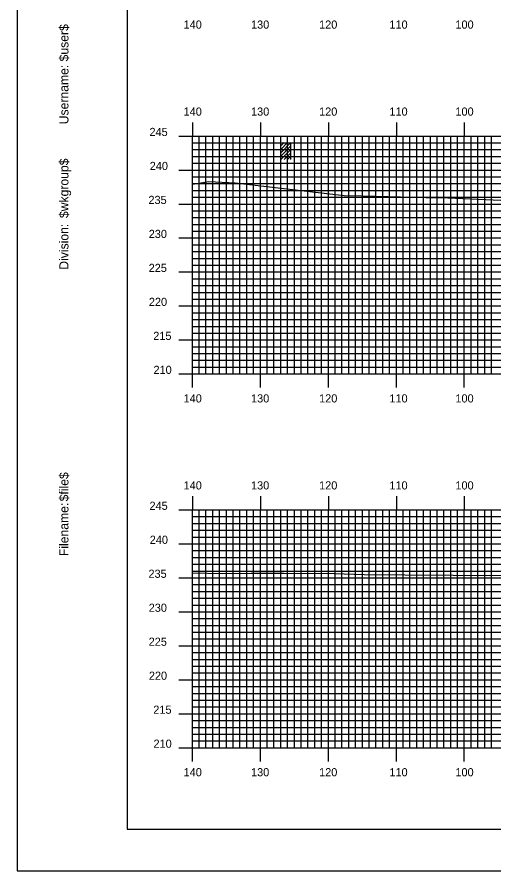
# Model space of a CAD drawing. Extents: x 1802323 to 1802666, y 442591 to 442811.
# Drawn here: x 1802322.8 to 1802393, y 442590.5 to 442716.2 of the extents above; entities that cross this region are included whole.
import ezdxf

# ---------------------------------------------------------------- set-up
doc = ezdxf.new("R2010")
doc.units = 0
for name, color, linetype in [('BORDER', 7, 'Continuous'), ('H_V ANNOTATION', 7, 'Continuous'), ('M_Buildings_Attachments', 7, 'Continuous'), ('MAJOR', 7, 'Continuous'), ('MINOR', 7, 'Continuous'), ('PLOT BOUNDARY', 7, 'Continuous'), ('S_Roadway_Centerline', 7, 'Continuous')]:
    doc.layers.add(name, color=color, linetype=linetype)

msp = doc.modelspace()

# ---------------------------------------------------------------- linework, layer by layer
at = {"layer": 'BORDER'}
msp.add_lwpolyline([(1802339, 442596.67), (1802659, 442596.67), (1802659, 442806.67), (1802339, 442806.67)], close=True, dxfattribs=at)
at = {"layer": 'M_Buildings_Attachments'}
for p, q in [((1802361.59, 442696.22), (1802363.1, 442697.73)), ((1802361.59, 442696.71), (1802362.57, 442697.73)), ((1802361.59, 442697.21), (1802362.08, 442697.73)), ((1802361.59, 442695.73), (1802363.1, 442697.21)), ((1802363.1, 442695.2), (1802363.1, 442697.73)), ((1802361.59, 442695.2), (1802363.1, 442696.71)), ((1802362.08, 442695.2), (1802363.1, 442696.22)), ((1802362.57, 442695.2), (1802363.1, 442695.73))]:
    msp.add_line(p, q, dxfattribs=at)
at = {"layer": 'MAJOR'}
for p, q in [((1802348.6, 442700.67), (1802348.6, 442698.67)), ((1802358.6, 442700.67), (1802358.6, 442698.67)), ((1802368.6, 442700.67), (1802368.6, 442698.67)), ((1802378.6, 442700.67), (1802378.6, 442698.67)), ((1802388.6, 442700.67), (1802388.6, 442698.67)), ((1802346.6, 442698.67), (1802348.6, 442698.67)), ((1802348.6, 442698.67), (1802628.6, 442698.67)), ((1802348.6, 442663.67), (1802348.6, 442698.67)), ((1802348.6, 442663.67), (1802348.6, 442698.67)), ((1802348.6, 442698.67), (1802628.6, 442698.67)), ((1802358.6, 442663.67), (1802358.6, 442698.67)), ((1802368.6, 442663.67), (1802368.6, 442698.67)), ((1802378.6, 442663.67), (1802378.6, 442698.67)), ((1802388.6, 442663.67), (1802388.6, 442698.67)), ((1802346.6, 442693.67), (1802348.6, 442693.67)), ((1802348.6, 442693.67), (1802628.6, 442693.67)), ((1802346.6, 442688.67), (1802348.6, 442688.67)), ((1802348.6, 442688.67), (1802628.6, 442688.67)), ((1802346.6, 442683.67), (1802348.6, 442683.67)), ((1802348.6, 442683.67), (1802628.6, 442683.67)), ((1802346.6, 442678.67), (1802348.6, 442678.67)), ((1802348.6, 442678.67), (1802628.6, 442678.67)), ((1802346.6, 442673.67), (1802348.6, 442673.67)), ((1802348.6, 442673.67), (1802628.6, 442673.67)), ((1802346.6, 442668.67), (1802348.6, 442668.67)), ((1802348.6, 442668.67), (1802628.6, 442668.67)), ((1802346.6, 442663.67), (1802348.6, 442663.67)), ((1802348.6, 442663.67), (1802628.6, 442663.67)), ((1802348.6, 442663.67), (1802628.6, 442663.67)), ((1802348.6, 442661.66), (1802348.6, 442663.67)), ((1802358.6, 442661.66), (1802358.6, 442663.67)), ((1802368.6, 442661.66), (1802368.6, 442663.67)), ((1802378.6, 442661.66), (1802378.6, 442663.67)), ((1802388.6, 442661.66), (1802388.6, 442663.67)), ((1802348.6, 442645.67), (1802348.6, 442643.67)), ((1802358.6, 442645.67), (1802358.6, 442643.67)), ((1802368.6, 442645.67), (1802368.6, 442643.67)), ((1802378.6, 442645.67), (1802378.6, 442643.67)), ((1802388.6, 442645.67), (1802388.6, 442643.67)), ((1802346.6, 442643.67), (1802348.6, 442643.67)), ((1802348.6, 442643.67), (1802628.6, 442643.67)), ((1802348.6, 442608.67), (1802348.6, 442643.67)), ((1802348.6, 442608.67), (1802348.6, 442643.67)), ((1802348.6, 442643.67), (1802628.6, 442643.67)), ((1802358.6, 442608.67), (1802358.6, 442643.67)), ((1802368.6, 442608.67), (1802368.6, 442643.67)), ((1802378.6, 442608.67), (1802378.6, 442643.67)), ((1802388.6, 442608.67), (1802388.6, 442643.67)), ((1802346.6, 442638.67), (1802348.6, 442638.67)), ((1802348.6, 442638.67), (1802628.6, 442638.67)), ((1802346.6, 442633.67), (1802348.6, 442633.67)), ((1802348.6, 442633.67), (1802628.6, 442633.67)), ((1802346.6, 442628.67), (1802348.6, 442628.67)), ((1802348.6, 442628.67), (1802628.6, 442628.67)), ((1802346.6, 442623.67), (1802348.6, 442623.67)), ((1802348.6, 442623.67), (1802628.6, 442623.67)), ((1802346.6, 442618.67), (1802348.6, 442618.67)), ((1802348.6, 442618.67), (1802628.6, 442618.67)), ((1802346.6, 442613.67), (1802348.6, 442613.67)), ((1802348.6, 442613.67), (1802628.6, 442613.67)), ((1802346.6, 442608.67), (1802348.6, 442608.67)), ((1802348.6, 442608.67), (1802628.6, 442608.67)), ((1802348.6, 442608.67), (1802628.6, 442608.67)), ((1802348.6, 442606.66), (1802348.6, 442608.67)), ((1802358.6, 442606.66), (1802358.6, 442608.67)), ((1802368.6, 442606.66), (1802368.6, 442608.67)), ((1802378.6, 442606.66), (1802378.6, 442608.67)), ((1802388.6, 442606.66), (1802388.6, 442608.67))]:
    msp.add_line(p, q, dxfattribs=at)
at = {"layer": 'MINOR'}
for p, q in [((1802349.6, 442663.67), (1802349.6, 442698.67)), ((1802350.6, 442663.67), (1802350.6, 442698.67)), ((1802351.6, 442663.67), (1802351.6, 442698.67)), ((1802352.6, 442663.67), (1802352.6, 442698.67)), ((1802353.6, 442663.67), (1802353.6, 442698.67)), ((1802354.6, 442663.67), (1802354.6, 442698.67)), ((1802355.6, 442663.67), (1802355.6, 442698.67)), ((1802356.6, 442663.67), (1802356.6, 442698.67)), ((1802357.6, 442663.67), (1802357.6, 442698.67)), ((1802359.6, 442663.67), (1802359.6, 442698.67)), ((1802360.6, 442663.67), (1802360.6, 442698.67)), ((1802361.6, 442663.67), (1802361.6, 442698.67)), ((1802362.6, 442663.67), (1802362.6, 442698.67)), ((1802363.6, 442663.67), (1802363.6, 442698.67)), ((1802364.6, 442663.67), (1802364.6, 442698.67)), ((1802365.6, 442663.67), (1802365.6, 442698.67)), ((1802366.6, 442663.67), (1802366.6, 442698.67)), ((1802367.6, 442663.67), (1802367.6, 442698.67)), ((1802369.6, 442663.67), (1802369.6, 442698.67)), ((1802370.6, 442663.67), (1802370.6, 442698.67)), ((1802371.6, 442663.67), (1802371.6, 442698.67)), ((1802372.6, 442663.67), (1802372.6, 442698.67)), ((1802373.6, 442663.67), (1802373.6, 442698.67)), ((1802374.6, 442663.67), (1802374.6, 442698.67)), ((1802375.6, 442663.67), (1802375.6, 442698.67)), ((1802376.6, 442663.67), (1802376.6, 442698.67)), ((1802377.6, 442663.67), (1802377.6, 442698.67)), ((1802379.6, 442663.67), (1802379.6, 442698.67)), ((1802380.6, 442663.67), (1802380.6, 442698.67)), ((1802381.6, 442663.67), (1802381.6, 442698.67)), ((1802382.6, 442663.67), (1802382.6, 442698.67)), ((1802383.6, 442663.67), (1802383.6, 442698.67)), ((1802384.6, 442663.67), (1802384.6, 442698.67)), ((1802385.6, 442663.67), (1802385.6, 442698.67)), ((1802386.6, 442663.67), (1802386.6, 442698.67)), ((1802387.6, 442663.67), (1802387.6, 442698.67)), ((1802389.6, 442663.67), (1802389.6, 442698.67)), ((1802390.6, 442663.67), (1802390.6, 442698.67)), ((1802391.6, 442663.67), (1802391.6, 442698.67)), ((1802392.6, 442663.67), (1802392.6, 442698.67)), ((1802348.6, 442697.67), (1802628.6, 442697.67)), ((1802348.6, 442697.67), (1802350.61, 442697.67)), ((1802348.6, 442696.67), (1802628.6, 442696.67)), ((1802348.6, 442696.67), (1802350.61, 442696.67)), ((1802348.6, 442695.67), (1802628.6, 442695.67)), ((1802348.6, 442695.67), (1802350.61, 442695.67)), ((1802348.6, 442694.67), (1802628.6, 442694.67)), ((1802348.6, 442694.67), (1802350.61, 442694.67)), ((1802348.6, 442692.67), (1802628.6, 442692.67)), ((1802348.6, 442692.67), (1802350.61, 442692.67)), ((1802348.6, 442691.67), (1802628.6, 442691.67)), ((1802348.6, 442691.67), (1802350.61, 442691.67)), ((1802348.6, 442690.67), (1802628.6, 442690.67)), ((1802348.6, 442690.67), (1802350.61, 442690.67)), ((1802348.6, 442689.67), (1802628.6, 442689.67)), ((1802348.6, 442689.67), (1802350.61, 442689.67)), ((1802348.6, 442687.67), (1802628.6, 442687.67)), ((1802348.6, 442687.67), (1802350.61, 442687.67)), ((1802348.6, 442686.67), (1802628.6, 442686.67)), ((1802348.6, 442686.67), (1802350.61, 442686.67)), ((1802348.6, 442685.67), (1802628.6, 442685.67)), ((1802348.6, 442685.67), (1802350.61, 442685.67)), ((1802348.6, 442684.67), (1802628.6, 442684.67)), ((1802348.6, 442684.67), (1802350.61, 442684.67)), ((1802348.6, 442682.67), (1802628.6, 442682.67)), ((1802348.6, 442682.67), (1802350.61, 442682.67)), ((1802348.6, 442681.67), (1802628.6, 442681.67)), ((1802348.6, 442681.67), (1802350.61, 442681.67)), ((1802348.6, 442680.67), (1802628.6, 442680.67)), ((1802348.6, 442680.67), (1802350.61, 442680.67)), ((1802348.6, 442679.67), (1802628.6, 442679.67)), ((1802348.6, 442679.67), (1802350.61, 442679.67)), ((1802348.6, 442677.67), (1802628.6, 442677.67)), ((1802348.6, 442677.67), (1802350.61, 442677.67)), ((1802348.6, 442676.67), (1802628.6, 442676.67)), ((1802348.6, 442676.67), (1802350.61, 442676.67)), ((1802348.6, 442675.67), (1802628.6, 442675.67)), ((1802348.6, 442675.67), (1802350.61, 442675.67)), ((1802348.6, 442674.67), (1802628.6, 442674.67)), ((1802348.6, 442674.67), (1802350.61, 442674.67)), ((1802348.6, 442672.67), (1802628.6, 442672.67)), ((1802348.6, 442672.67), (1802350.61, 442672.67)), ((1802348.6, 442671.67), (1802628.6, 442671.67)), ((1802348.6, 442671.67), (1802350.61, 442671.67)), ((1802348.6, 442670.67), (1802628.6, 442670.67)), ((1802348.6, 442670.67), (1802350.61, 442670.67)), ((1802348.6, 442669.67), (1802628.6, 442669.67)), ((1802348.6, 442669.67), (1802350.61, 442669.67)), ((1802348.6, 442667.67), (1802628.6, 442667.67)), ((1802348.6, 442667.67), (1802350.61, 442667.67)), ((1802348.6, 442666.67), (1802628.6, 442666.67)), ((1802348.6, 442666.67), (1802350.61, 442666.67)), ((1802348.6, 442665.67), (1802628.6, 442665.67)), ((1802348.6, 442665.67), (1802350.61, 442665.67)), ((1802348.6, 442664.67), (1802628.6, 442664.67)), ((1802348.6, 442664.67), (1802350.61, 442664.67)), ((1802349.6, 442608.67), (1802349.6, 442643.67)), ((1802350.6, 442608.67), (1802350.6, 442643.67)), ((1802351.6, 442608.67), (1802351.6, 442643.67)), ((1802352.6, 442608.67), (1802352.6, 442643.67)), ((1802353.6, 442608.67), (1802353.6, 442643.67)), ((1802354.6, 442608.67), (1802354.6, 442643.67)), ((1802355.6, 442608.67), (1802355.6, 442643.67)), ((1802356.6, 442608.67), (1802356.6, 442643.67)), ((1802357.6, 442608.67), (1802357.6, 442643.67)), ((1802359.6, 442608.67), (1802359.6, 442643.67)), ((1802360.6, 442608.67), (1802360.6, 442643.67)), ((1802361.6, 442608.67), (1802361.6, 442643.67)), ((1802362.6, 442608.67), (1802362.6, 442643.67)), ((1802363.6, 442608.67), (1802363.6, 442643.67)), ((1802364.6, 442608.67), (1802364.6, 442643.67)), ((1802365.6, 442608.67), (1802365.6, 442643.67)), ((1802366.6, 442608.67), (1802366.6, 442643.67)), ((1802367.6, 442608.67), (1802367.6, 442643.67)), ((1802369.6, 442608.67), (1802369.6, 442643.67)), ((1802370.6, 442608.67), (1802370.6, 442643.67)), ((1802371.6, 442608.67), (1802371.6, 442643.67)), ((1802372.6, 442608.67), (1802372.6, 442643.67)), ((1802373.6, 442608.67), (1802373.6, 442643.67)), ((1802374.6, 442608.67), (1802374.6, 442643.67)), ((1802375.6, 442608.67), (1802375.6, 442643.67)), ((1802376.6, 442608.67), (1802376.6, 442643.67)), ((1802377.6, 442608.67), (1802377.6, 442643.67)), ((1802379.6, 442608.67), (1802379.6, 442643.67)), ((1802380.6, 442608.67), (1802380.6, 442643.67)), ((1802381.6, 442608.67), (1802381.6, 442643.67)), ((1802382.6, 442608.67), (1802382.6, 442643.67)), ((1802383.6, 442608.67), (1802383.6, 442643.67)), ((1802384.6, 442608.67), (1802384.6, 442643.67)), ((1802385.6, 442608.67), (1802385.6, 442643.67)), ((1802386.6, 442608.67), (1802386.6, 442643.67)), ((1802387.6, 442608.67), (1802387.6, 442643.67)), ((1802389.6, 442608.67), (1802389.6, 442643.67)), ((1802390.6, 442608.67), (1802390.6, 442643.67)), ((1802391.6, 442608.67), (1802391.6, 442643.67)), ((1802392.6, 442608.67), (1802392.6, 442643.67)), ((1802348.6, 442642.67), (1802628.6, 442642.67)), ((1802348.6, 442642.67), (1802350.61, 442642.67)), ((1802348.6, 442641.67), (1802628.6, 442641.67)), ((1802348.6, 442641.67), (1802350.61, 442641.67)), ((1802348.6, 442640.67), (1802628.6, 442640.67)), ((1802348.6, 442640.67), (1802350.61, 442640.67)), ((1802348.6, 442639.67), (1802628.6, 442639.67)), ((1802348.6, 442639.67), (1802350.61, 442639.67)), ((1802348.6, 442637.67), (1802628.6, 442637.67)), ((1802348.6, 442637.67), (1802350.61, 442637.67)), ((1802348.6, 442636.67), (1802628.6, 442636.67)), ((1802348.6, 442636.67), (1802350.61, 442636.67)), ((1802348.6, 442635.67), (1802628.6, 442635.67)), ((1802348.6, 442635.67), (1802350.61, 442635.67)), ((1802348.6, 442634.67), (1802628.6, 442634.67)), ((1802348.6, 442634.67), (1802350.61, 442634.67)), ((1802348.6, 442632.67), (1802628.6, 442632.67)), ((1802348.6, 442632.67), (1802350.61, 442632.67)), ((1802348.6, 442631.67), (1802628.6, 442631.67)), ((1802348.6, 442631.67), (1802350.61, 442631.67)), ((1802348.6, 442630.67), (1802628.6, 442630.67)), ((1802348.6, 442630.67), (1802350.61, 442630.67)), ((1802348.6, 442629.67), (1802628.6, 442629.67)), ((1802348.6, 442629.67), (1802350.61, 442629.67)), ((1802348.6, 442627.67), (1802628.6, 442627.67)), ((1802348.6, 442627.67), (1802350.61, 442627.67)), ((1802348.6, 442626.67), (1802628.6, 442626.67)), ((1802348.6, 442626.67), (1802350.61, 442626.67)), ((1802348.6, 442625.67), (1802628.6, 442625.67)), ((1802348.6, 442625.67), (1802350.61, 442625.67)), ((1802348.6, 442624.67), (1802628.6, 442624.67)), ((1802348.6, 442624.67), (1802350.61, 442624.67)), ((1802348.6, 442622.67), (1802628.6, 442622.67)), ((1802348.6, 442622.67), (1802350.61, 442622.67)), ((1802348.6, 442621.67), (1802628.6, 442621.67)), ((1802348.6, 442621.67), (1802350.61, 442621.67)), ((1802348.6, 442620.67), (1802628.6, 442620.67)), ((1802348.6, 442620.67), (1802350.61, 442620.67)), ((1802348.6, 442619.67), (1802628.6, 442619.67)), ((1802348.6, 442619.67), (1802350.61, 442619.67)), ((1802348.6, 442617.67), (1802628.6, 442617.67)), ((1802348.6, 442617.67), (1802350.61, 442617.67)), ((1802348.6, 442616.67), (1802628.6, 442616.67)), ((1802348.6, 442616.67), (1802350.61, 442616.67)), ((1802348.6, 442615.67), (1802628.6, 442615.67)), ((1802348.6, 442615.67), (1802350.61, 442615.67)), ((1802348.6, 442614.67), (1802628.6, 442614.67)), ((1802348.6, 442614.67), (1802350.61, 442614.67)), ((1802348.6, 442612.67), (1802628.6, 442612.67)), ((1802348.6, 442612.67), (1802350.61, 442612.67)), ((1802348.6, 442611.67), (1802628.6, 442611.67)), ((1802348.6, 442611.67), (1802350.61, 442611.67)), ((1802348.6, 442610.67), (1802628.6, 442610.67)), ((1802348.6, 442610.67), (1802350.61, 442610.67)), ((1802348.6, 442609.67), (1802628.6, 442609.67)), ((1802348.6, 442609.67), (1802350.61, 442609.67))]:
    msp.add_line(p, q, dxfattribs=at)
at = {"layer": 'PLOT BOUNDARY'}
msp.add_lwpolyline([(1802322.81, 442590.55), (1802662.81, 442590.55), (1802662.81, 442810.55), (1802322.81, 442810.55)], close=True, dxfattribs=at)
at = {"layer": 'S_Roadway_Centerline'}
for points in [[(1802348.6, 442691.61), (1802351.02, 442691.99), (1802354.91, 442691.79), (1802370.93, 442689.91), (1802373.69, 442689.86), (1802382.93, 442689.63), (1802384.45, 442689.61), (1802386.15, 442689.57), (1802393.97, 442689.24)], [(1802348.6, 442634.4), (1802352.96, 442634.32), (1802357.25, 442634.36), (1802362.06, 442634.34), (1802369.45, 442634.3), (1802373.86, 442634.18), (1802379.85, 442634.11), (1802386.95, 442634.08), (1802395.18, 442633.99)]]:
    msp.add_lwpolyline(points, dxfattribs=at)

# ---------------------------------------------------------------- texts
at = {"layer": 'BORDER'}
for s, p in [('$user$', (1802330.37, 442709.65)), ('Username:', (1802330.37, 442700.4)), ('$wkgroup$', (1802330.37, 442686.6)), ('Division:', (1802330.37, 442679)), ('$file$', (1802330.37, 442644.92)), ('Filename:', (1802330.37, 442636.86))]:
    msp.add_text(s, height=1.339, rotation=90, dxfattribs=at).set_placement(p)
at = {"layer": 'H_V ANNOTATION'}
for s, p in [('140', (1802347.31, 442714.47)), ('130', (1802357.23, 442714.47)), ('120', (1802367.24, 442714.47)), ('110', (1802377.58, 442714.47)), ('100', (1802387.29, 442714.47)), ('140', (1802347.31, 442701.67)), ('130', (1802357.23, 442701.67)), ('120', (1802367.24, 442701.67)), ('110', (1802377.58, 442701.67)), ('100', (1802387.29, 442701.67)), ('245', (1802342.29, 442698.67)), ('240', (1802342.33, 442693.67)), ('235', (1802342.14, 442688.67)), ('230', (1802342.18, 442683.67)), ('225', (1802342.17, 442678.67)), ('220', (1802342.2, 442673.67)), ('215', (1802342.85, 442668.67)), ('210', (1802342.88, 442663.67)), ('140', (1802347.31, 442659.47)), ('130', (1802357.23, 442659.47)), ('120', (1802367.24, 442659.47)), ('110', (1802377.58, 442659.47)), ('100', (1802387.29, 442659.47)), ('140', (1802347.31, 442646.67)), ('130', (1802357.23, 442646.67)), ('120', (1802367.24, 442646.67)), ('110', (1802377.58, 442646.67)), ('100', (1802387.29, 442646.67)), ('245', (1802342.29, 442643.67)), ('240', (1802342.33, 442638.67)), ('235', (1802342.14, 442633.67)), ('230', (1802342.18, 442628.67)), ('225', (1802342.17, 442623.67)), ('220', (1802342.2, 442618.67)), ('215', (1802342.85, 442613.67)), ('210', (1802342.88, 442608.67)), ('140', (1802347.31, 442604.47)), ('130', (1802357.23, 442604.47)), ('120', (1802367.24, 442604.47)), ('110', (1802377.58, 442604.47)), ('100', (1802387.29, 442604.47))]:
    msp.add_text(s, height=1.2, dxfattribs=at).set_placement(p)
at = {"layer": 'MAJOR'}
for p in [(1802348.59, 442663.67), (1802348.59, 442608.67)]:
    msp.add_text('-', height=0.012, dxfattribs=at).set_placement(p)

doc.saveas('drawing.dxf')
